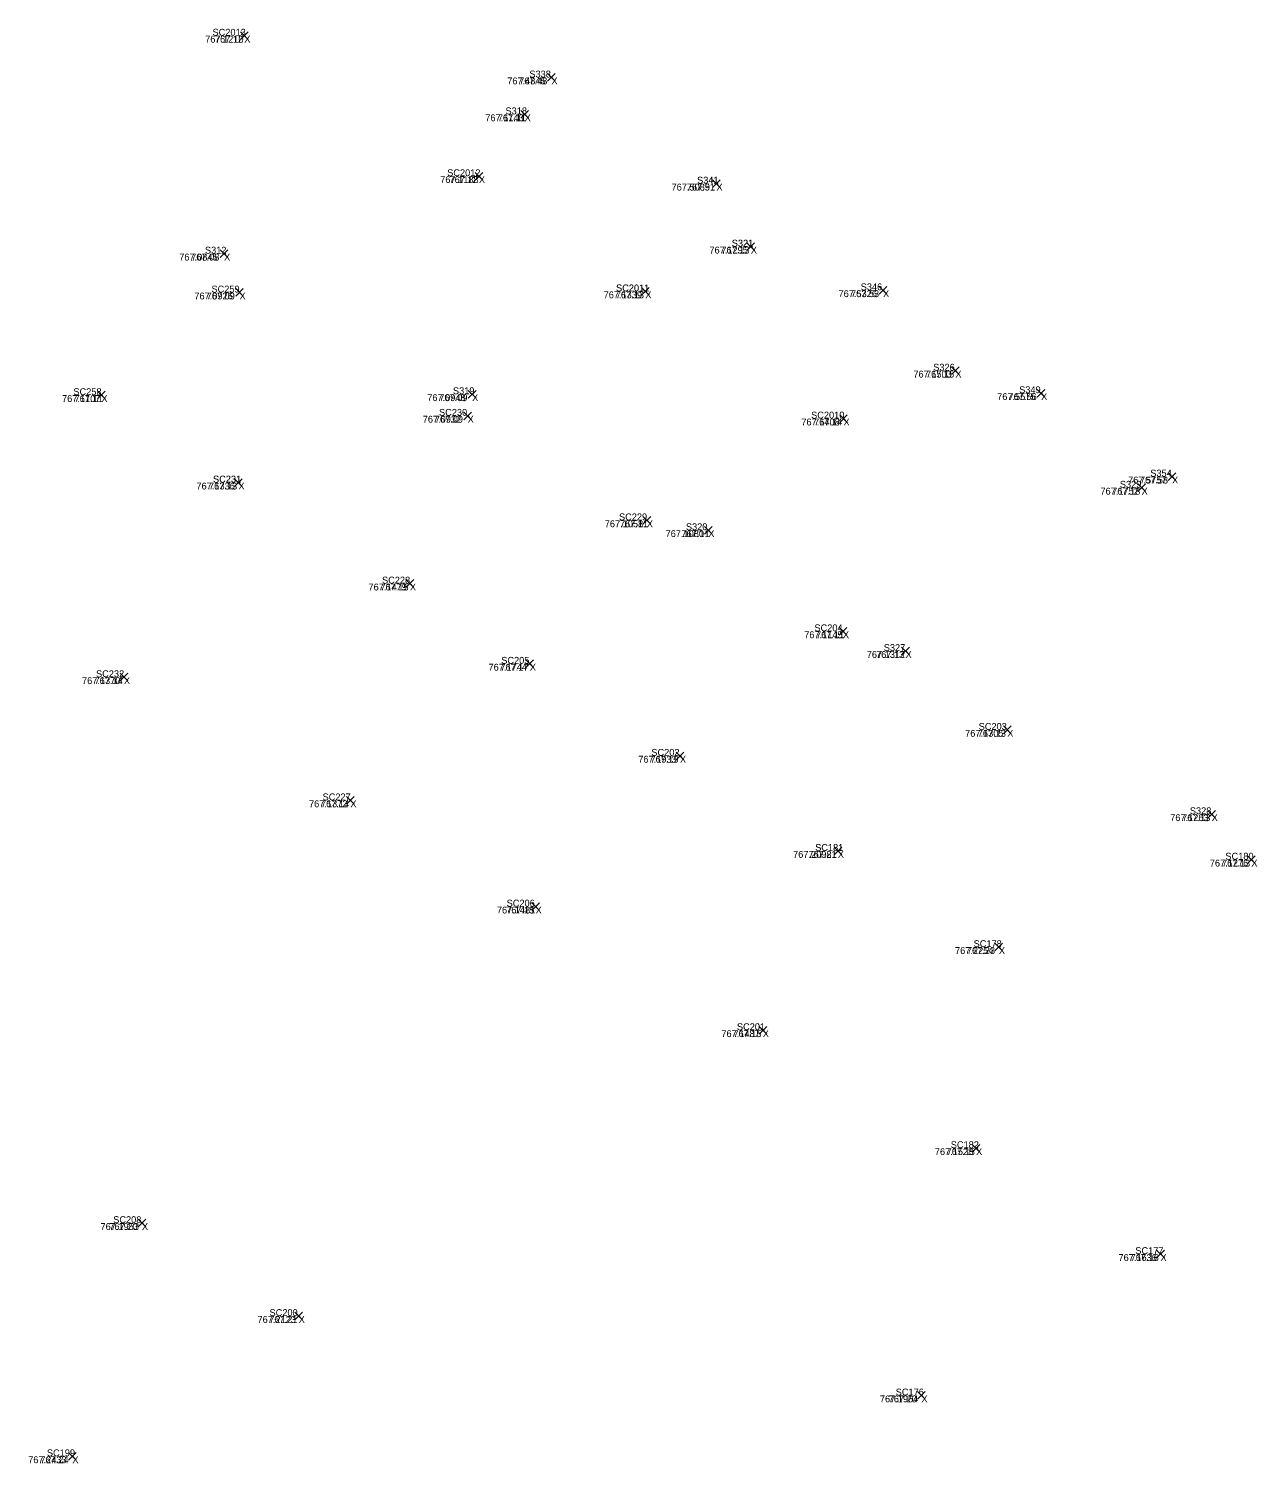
# Model space of a CAD drawing. Extents: x 1845019 to 1877956, y 680444 to 701081.
# Drawn here: x 1857674 to 1857684.7, y 694277.53 to 694290.04 of the extents above; entities that cross this region are included whole.
import ezdxf

# ---------------------------------------------------------------- set-up
doc = ezdxf.new("R2010")
doc.units = 0
for name, color, linetype in [('SV_X_Random_Point', 7, 'Continuous'), ('SV_X_Text_Comment', 7, 'Continuous'), ('SV_X_Text_Elevation', 7, 'Continuous'), ('SV_X_Text_Name', 7, 'Continuous')]:
    doc.layers.add(name, color=color, linetype=linetype)

msp = doc.modelspace()

# ---------------------------------------------------------------- linework, layer by layer
at = {"layer": 'SV_X_Random_Point'}
for p, q in [((1857675.845, 694289.941), (1857675.912, 694290.008)), ((1857675.845, 694290.008), (1857675.912, 694289.941)), ((1857675.845, 694289.941), (1857675.912, 694290.008)), ((1857675.845, 694290.008), (1857675.912, 694289.941)), ((1857678.521, 694289.577), (1857678.588, 694289.644)), ((1857678.521, 694289.644), (1857678.588, 694289.577)), ((1857678.521, 694289.577), (1857678.588, 694289.644)), ((1857678.521, 694289.644), (1857678.588, 694289.577)), ((1857678.287, 694289.255), (1857678.354, 694289.322)), ((1857678.287, 694289.322), (1857678.354, 694289.255)), ((1857678.287, 694289.255), (1857678.354, 694289.322)), ((1857678.287, 694289.322), (1857678.354, 694289.255)), ((1857677.889, 694288.716), (1857677.956, 694288.783)), ((1857677.889, 694288.783), (1857677.956, 694288.716)), ((1857677.889, 694288.716), (1857677.956, 694288.783)), ((1857677.889, 694288.783), (1857677.956, 694288.716)), ((1857679.958, 694288.651), (1857680.025, 694288.718)), ((1857679.958, 694288.718), (1857680.025, 694288.651)), ((1857679.958, 694288.651), (1857680.025, 694288.718)), ((1857679.958, 694288.718), (1857680.025, 694288.651)), ((1857680.258, 694288.103), (1857680.325, 694288.17)), ((1857680.258, 694288.17), (1857680.325, 694288.103)), ((1857680.258, 694288.103), (1857680.325, 694288.17)), ((1857680.258, 694288.17), (1857680.325, 694288.103)), ((1857675.668, 694288.042), (1857675.735, 694288.108)), ((1857675.668, 694288.108), (1857675.735, 694288.042)), ((1857675.668, 694288.042), (1857675.735, 694288.108)), ((1857675.668, 694288.108), (1857675.735, 694288.042)), ((1857675.803, 694287.703), (1857675.869, 694287.77)), ((1857675.803, 694287.77), (1857675.869, 694287.703)), ((1857675.803, 694287.703), (1857675.869, 694287.77)), ((1857675.803, 694287.77), (1857675.869, 694287.703)), ((1857679.339, 694287.712), (1857679.405, 694287.779)), ((1857679.339, 694287.779), (1857679.405, 694287.712)), ((1857679.339, 694287.712), (1857679.405, 694287.779)), ((1857679.339, 694287.779), (1857679.405, 694287.712)), ((1857681.411, 694287.723), (1857681.477, 694287.79)), ((1857681.411, 694287.79), (1857681.477, 694287.723)), ((1857681.411, 694287.723), (1857681.477, 694287.79)), ((1857681.411, 694287.79), (1857681.477, 694287.723)), ((1857682.041, 694287.021), (1857682.107, 694287.088)), ((1857682.041, 694287.088), (1857682.107, 694287.021)), ((1857682.041, 694287.021), (1857682.107, 694287.088)), ((1857682.041, 694287.088), (1857682.107, 694287.021)), ((1857674.599, 694286.809), (1857674.666, 694286.876)), ((1857674.599, 694286.876), (1857674.666, 694286.809)), ((1857674.599, 694286.809), (1857674.666, 694286.876)), ((1857674.599, 694286.876), (1857674.666, 694286.809)), ((1857677.83, 694286.816), (1857677.897, 694286.883)), ((1857677.83, 694286.883), (1857677.897, 694286.816)), ((1857677.83, 694286.816), (1857677.897, 694286.883)), ((1857677.83, 694286.883), (1857677.897, 694286.816)), ((1857682.788, 694286.825), (1857682.854, 694286.892)), ((1857682.788, 694286.892), (1857682.854, 694286.825)), ((1857682.788, 694286.825), (1857682.854, 694286.892)), ((1857682.788, 694286.892), (1857682.854, 694286.825)), ((1857677.791, 694286.628), (1857677.857, 694286.695)), ((1857677.791, 694286.695), (1857677.857, 694286.628)), ((1857677.791, 694286.628), (1857677.857, 694286.695)), ((1857677.791, 694286.695), (1857677.857, 694286.628)), ((1857681.066, 694286.604), (1857681.132, 694286.671)), ((1857681.066, 694286.671), (1857681.132, 694286.604)), ((1857681.066, 694286.604), (1857681.132, 694286.671)), ((1857681.066, 694286.671), (1857681.132, 694286.604)), ((1857683.929, 694286.099), (1857683.996, 694286.165)), ((1857683.929, 694286.165), (1857683.996, 694286.099)), ((1857683.929, 694286.099), (1857683.996, 694286.165)), ((1857683.929, 694286.165), (1857683.996, 694286.099)), ((1857675.794, 694286.047), (1857675.86, 694286.113)), ((1857675.794, 694286.113), (1857675.86, 694286.047)), ((1857675.794, 694286.047), (1857675.86, 694286.113)), ((1857675.794, 694286.113), (1857675.86, 694286.047)), ((1857683.664, 694286.001), (1857683.731, 694286.068)), ((1857683.664, 694286.068), (1857683.731, 694286.001)), ((1857683.664, 694286.001), (1857683.731, 694286.068)), ((1857683.664, 694286.068), (1857683.731, 694286.001)), ((1857679.352, 694285.718), (1857679.419, 694285.785)), ((1857679.352, 694285.785), (1857679.419, 694285.718)), ((1857679.352, 694285.718), (1857679.419, 694285.785)), ((1857679.352, 694285.785), (1857679.419, 694285.718)), ((1857679.887, 694285.631), (1857679.954, 694285.698)), ((1857679.887, 694285.698), (1857679.954, 694285.631)), ((1857679.887, 694285.631), (1857679.954, 694285.698)), ((1857679.887, 694285.698), (1857679.954, 694285.631)), ((1857677.287, 694285.167), (1857677.354, 694285.234)), ((1857677.287, 694285.234), (1857677.354, 694285.167)), ((1857677.287, 694285.167), (1857677.354, 694285.234)), ((1857677.287, 694285.234), (1857677.354, 694285.167)), ((1857681.061, 694284.751), (1857681.127, 694284.817)), ((1857681.061, 694284.817), (1857681.127, 694284.751)), ((1857681.061, 694284.751), (1857681.127, 694284.817)), ((1857681.061, 694284.817), (1857681.127, 694284.751)), ((1857681.606, 694284.579), (1857681.673, 694284.645)), ((1857681.606, 694284.645), (1857681.673, 694284.579)), ((1857681.606, 694284.579), (1857681.673, 694284.645)), ((1857681.606, 694284.645), (1857681.673, 694284.579)), ((1857678.332, 694284.468), (1857678.399, 694284.534)), ((1857678.332, 694284.534), (1857678.399, 694284.468)), ((1857678.332, 694284.468), (1857678.399, 694284.534)), ((1857678.332, 694284.534), (1857678.399, 694284.468)), ((1857674.796, 694284.351), (1857674.863, 694284.418)), ((1857674.796, 694284.418), (1857674.863, 694284.351)), ((1857674.796, 694284.351), (1857674.863, 694284.418)), ((1857674.796, 694284.418), (1857674.863, 694284.351)), ((1857682.492, 694283.892), (1857682.559, 694283.959)), ((1857682.492, 694283.959), (1857682.559, 694283.892)), ((1857682.492, 694283.892), (1857682.559, 694283.959)), ((1857682.492, 694283.959), (1857682.559, 694283.892)), ((1857679.64, 694283.665), (1857679.707, 694283.732)), ((1857679.64, 694283.732), (1857679.707, 694283.665)), ((1857679.64, 694283.665), (1857679.707, 694283.732)), ((1857679.64, 694283.732), (1857679.707, 694283.665)), ((1857676.769, 694283.278), (1857676.835, 694283.344)), ((1857676.769, 694283.344), (1857676.835, 694283.278)), ((1857676.769, 694283.278), (1857676.835, 694283.344)), ((1857676.769, 694283.344), (1857676.835, 694283.278)), ((1857684.273, 694283.157), (1857684.34, 694283.223)), ((1857684.273, 694283.223), (1857684.34, 694283.157)), ((1857684.273, 694283.157), (1857684.34, 694283.223)), ((1857684.273, 694283.223), (1857684.34, 694283.157)), ((1857681.017, 694282.837), (1857681.084, 694282.903)), ((1857681.017, 694282.903), (1857681.084, 694282.837)), ((1857681.017, 694282.837), (1857681.084, 694282.903)), ((1857681.017, 694282.903), (1857681.084, 694282.837)), ((1857684.62, 694282.76), (1857684.686, 694282.827)), ((1857684.62, 694282.827), (1857684.686, 694282.76)), ((1857684.62, 694282.76), (1857684.686, 694282.827)), ((1857684.62, 694282.827), (1857684.686, 694282.76)), ((1857678.383, 694282.352), (1857678.45, 694282.418)), ((1857678.383, 694282.418), (1857678.45, 694282.352)), ((1857678.383, 694282.352), (1857678.45, 694282.418)), ((1857678.383, 694282.418), (1857678.45, 694282.352)), ((1857682.419, 694281.999), (1857682.486, 694282.065)), ((1857682.419, 694282.065), (1857682.486, 694281.999)), ((1857682.419, 694281.999), (1857682.486, 694282.065)), ((1857682.419, 694282.065), (1857682.486, 694281.999)), ((1857680.363, 694281.274), (1857680.43, 694281.341)), ((1857680.363, 694281.341), (1857680.43, 694281.274)), ((1857680.363, 694281.274), (1857680.43, 694281.341)), ((1857680.363, 694281.341), (1857680.43, 694281.274)), ((1857682.221, 694280.246), (1857682.288, 694280.313)), ((1857682.221, 694280.313), (1857682.288, 694280.246)), ((1857682.221, 694280.246), (1857682.288, 694280.313)), ((1857682.221, 694280.313), (1857682.288, 694280.246)), ((1857674.953, 694279.594), (1857675.019, 694279.661)), ((1857674.953, 694279.661), (1857675.019, 694279.594)), ((1857674.953, 694279.594), (1857675.019, 694279.661)), ((1857674.953, 694279.661), (1857675.019, 694279.594)), ((1857683.828, 694279.323), (1857683.895, 694279.39)), ((1857683.828, 694279.39), (1857683.895, 694279.323)), ((1857683.828, 694279.323), (1857683.895, 694279.39)), ((1857683.828, 694279.39), (1857683.895, 694279.323)), ((1857676.319, 694278.783), (1857676.385, 694278.85)), ((1857676.319, 694278.85), (1857676.385, 694278.783)), ((1857676.319, 694278.783), (1857676.385, 694278.85)), ((1857676.319, 694278.85), (1857676.385, 694278.783)), ((1857681.744, 694278.092), (1857681.811, 694278.159)), ((1857681.744, 694278.159), (1857681.811, 694278.092)), ((1857681.744, 694278.092), (1857681.811, 694278.159)), ((1857681.744, 694278.159), (1857681.811, 694278.092)), ((1857674.346, 694277.561), (1857674.413, 694277.628)), ((1857674.346, 694277.628), (1857674.413, 694277.561)), ((1857674.346, 694277.561), (1857674.413, 694277.628)), ((1857674.346, 694277.628), (1857674.413, 694277.561))]:
    msp.add_line(p, q, dxfattribs=at)

# ---------------------------------------------------------------- texts
at = {"layer": 'SV_X_Text_Comment'}
for p in [(1857675.878, 694289.914), (1857678.554, 694289.55), (1857678.321, 694289.229), (1857677.922, 694288.69), (1857679.992, 694288.625), (1857680.292, 694288.076), (1857675.702, 694288.015), (1857681.444, 694287.696), (1857675.836, 694287.676), (1857679.372, 694287.686), (1857682.074, 694286.995), (1857674.633, 694286.782), (1857677.863, 694286.79), (1857682.821, 694286.799), (1857677.824, 694286.602), (1857681.099, 694286.578), (1857683.962, 694286.072), (1857675.827, 694286.02), (1857683.697, 694285.975), (1857679.385, 694285.691), (1857679.921, 694285.605), (1857677.321, 694285.14), (1857681.094, 694284.724), (1857678.366, 694284.441), (1857681.64, 694284.552), (1857674.829, 694284.324), (1857682.526, 694283.865), (1857679.674, 694283.639), (1857676.802, 694283.251), (1857684.307, 694283.13), (1857681.05, 694282.81), (1857684.653, 694282.734), (1857678.416, 694282.325), (1857682.453, 694281.972), (1857680.396, 694281.248), (1857682.255, 694280.22), (1857674.986, 694279.567), (1857683.861, 694279.297), (1857676.352, 694278.757), (1857681.778, 694278.065), (1857674.38, 694277.535)]:
    msp.add_text('X', height=0.06, dxfattribs=at).set_placement(p)
at = {"layer": 'SV_X_Text_Elevation'}
for s, p in [('767.1210', (1857675.537, 694289.914)), ('767.12', (1857675.622, 694289.914)), ('767.4845', (1857678.169, 694289.55)), ('767.48', (1857678.273, 694289.55)), ('767.1140', (1857677.978, 694289.229)), ('767.11', (1857678.087, 694289.229)), ('767.1188', (1857677.585, 694288.69)), ('767.12', (1857677.666, 694288.69)), ('767.5089', (1857679.601, 694288.625)), ('767.51', (1857679.734, 694288.625)), ('767.1295', (1857679.931, 694288.076)), ('767.13', (1857680.035, 694288.076)), ('767.0845', (1857675.311, 694288.015)), ('767.08', (1857675.415, 694288.015)), ('767.5326', (1857681.056, 694287.696)), ('767.53', (1857681.164, 694287.696)), ('767.0926', (1857675.443, 694287.676)), ('767.09', (1857675.55, 694287.676)), ('767.1339', (1857679.009, 694287.686)), ('767.13', (1857679.115, 694287.686)), ('767.1503', (1857681.708, 694286.995)), ('767.15', (1857681.818, 694286.995)), ('767.1107', (1857674.29, 694286.782)), ('767.11', (1857674.399, 694286.782)), ('767.0948', (1857677.472, 694286.79)), ('767.09', (1857677.577, 694286.79)), ('767.5575', (1857682.438, 694286.799)), ('767.56', (1857682.537, 694286.799)), ('767.0932', (1857677.433, 694286.602)), ('767.09', (1857677.538, 694286.602)), ('767.1408', (1857680.732, 694286.578)), ('767.14', (1857680.843, 694286.578)), ('767.5757', (1857683.579, 694286.072)), ('767.58', (1857683.682, 694286.072)), ('767.1336', (1857675.461, 694286.02)), ('767.13', (1857675.57, 694286.02)), ('767.1752', (1857683.338, 694285.975)), ('767.18', (1857683.44, 694285.975)), ('767.1058', (1857679.019, 694285.691)), ('767.11', (1857679.151, 694285.691)), ('767.1080', (1857679.549, 694285.605)), ('767.11', (1857679.687, 694285.605)), ('767.1479', (1857676.96, 694285.14)), ('767.15', (1857677.064, 694285.14)), ('767.1145', (1857680.757, 694284.724)), ('767.11', (1857680.86, 694284.724)), ('767.1744', (1857678.006, 694284.441)), ('767.17', (1857678.109, 694284.441)), ('767.1312', (1857681.302, 694284.552)), ('767.13', (1857681.383, 694284.552)), ('767.1370', (1857674.464, 694284.324)), ('767.14', (1857674.573, 694284.324)), ('767.1305', (1857682.159, 694283.865)), ('767.13', (1857682.269, 694283.865)), ('767.1933', (1857679.311, 694283.639)), ('767.19', (1857679.417, 694283.639)), ('767.1372', (1857676.442, 694283.251)), ('767.14', (1857676.546, 694283.251)), ('767.1263', (1857683.946, 694283.13)), ('767.13', (1857684.05, 694283.13)), ('767.2098', (1857680.66, 694282.81)), ('767.21', (1857680.794, 694282.81)), ('767.1276', (1857684.291, 694282.734)), ('767.13', (1857684.397, 694282.734)), ('767.1481', (1857678.079, 694282.325)), ('767.15', (1857678.16, 694282.325)), ('767.2254', (1857682.071, 694281.972)), ('767.23', (1857682.174, 694281.972)), ('767.1487', (1857680.035, 694281.248)), ('767.15', (1857680.14, 694281.248)), ('767.1528', (1857681.895, 694280.22)), ('767.15', (1857681.998, 694280.22)), ('767.1953', (1857674.625, 694279.567)), ('767.20', (1857674.702, 694279.567)), ('767.1636', (1857683.495, 694279.297)), ('767.16', (1857683.601, 694279.297)), ('767.2123', (1857675.993, 694278.757)), ('767.21', (1857676.095, 694278.757)), ('767.1964', (1857681.416, 694278.065)), ('767.20', (1857681.493, 694278.065)), ('767.2433', (1857673.995, 694277.535)), ('767.24', (1857674.101, 694277.535))]:
    msp.add_text(s, height=0.06, dxfattribs=at).set_placement(p)
at = {"layer": 'SV_X_Text_Name'}
for s, p in [('SC2013', (1857675.601, 694289.974)), ('SC2013', (1857675.601, 694289.974)), ('S338', (1857678.362, 694289.61)), ('S338', (1857678.362, 694289.61)), ('S318', (1857678.154, 694289.289)), ('S318', (1857678.154, 694289.289)), ('SC2012', (1857677.646, 694288.75)), ('SC2012', (1857677.646, 694288.75)), ('S341', (1857679.823, 694288.685)), ('S341', (1857679.824, 694288.685)), ('S312', (1857675.535, 694288.075)), ('S312', (1857675.535, 694288.075)), ('S321', (1857680.125, 694288.136)), ('S321', (1857680.126, 694288.136)), ('SC259', (1857675.592, 694287.736)), ('SC259', (1857675.592, 694287.736)), ('SC2011', (1857679.117, 694287.746)), ('SC2011', (1857679.118, 694287.746)), ('S346', (1857681.249, 694287.756)), ('S346', (1857681.249, 694287.756)), ('S326', (1857681.881, 694287.055)), ('S326', (1857681.881, 694287.055)), ('SC258', (1857674.389, 694286.842)), ('SC258', (1857674.389, 694286.842)), ('S319', (1857677.696, 694286.85)), ('S319', (1857677.696, 694286.85)), ('S349', (1857682.63, 694286.859)), ('S349', (1857682.63, 694286.859)), ('SC230', (1857677.575, 694286.662)), ('SC230', (1857677.575, 694286.662)), ('SC2010', (1857680.817, 694286.638)), ('SC2010', (1857680.817, 694286.638)), ('SC231', (1857675.605, 694286.08)), ('SC231', (1857675.606, 694286.08)), ('S354', (1857683.772, 694286.132)), ('S354', (1857683.772, 694286.132)), ('S329', (1857683.507, 694286.035)), ('S329', (1857683.507, 694286.035)), ('SC229', (1857679.143, 694285.751)), ('SC229', (1857679.143, 694285.751)), ('S320', (1857679.726, 694285.665)), ('S320', (1857679.726, 694285.665)), ('SC228', (1857677.078, 694285.2)), ('SC228', (1857677.078, 694285.2)), ('SC204', (1857680.846, 694284.784)), ('SC204', (1857680.846, 694284.784)), ('S327', (1857681.45, 694284.612)), ('S327', (1857681.45, 694284.612)), ('SC205', (1857678.117, 694284.501)), ('SC205', (1857678.117, 694284.501)), ('SC232', (1857674.586, 694284.384)), ('SC232', (1857674.586, 694284.384)), ('SC203', (1857682.277, 694283.925)), ('SC203', (1857682.277, 694283.925)), ('SC202', (1857679.425, 694283.699)), ('SC202', (1857679.425, 694283.699)), ('SC227', (1857676.56, 694283.311)), ('SC227', (1857676.56, 694283.311)), ('S328', (1857684.117, 694283.19)), ('S328', (1857684.117, 694283.19)), ('SC181', (1857680.852, 694282.87)), ('SC181', (1857680.853, 694282.87)), ('SC180', (1857684.427, 694282.794)), ('SC180', (1857684.427, 694282.794)), ('SC206', (1857678.164, 694282.385)), ('SC206', (1857678.164, 694282.385)), ('SC178', (1857682.233, 694282.032)), ('SC178', (1857682.233, 694282.032)), ('SC201', (1857680.17, 694281.308)), ('SC201', (1857680.171, 694281.308)), ('SC182', (1857682.034, 694280.28)), ('SC182', (1857682.034, 694280.28)), ('SC208', (1857674.736, 694279.627)), ('SC208', (1857674.736, 694279.627)), ('SC177', (1857683.642, 694279.357)), ('SC177', (1857683.642, 694279.357)), ('SC200', (1857676.098, 694278.817)), ('SC200', (1857676.098, 694278.817)), ('SC176', (1857681.554, 694278.125)), ('SC176', (1857681.554, 694278.125)), ('SC199', (1857674.158, 694277.595)), ('SC199', (1857674.158, 694277.595))]:
    msp.add_text(s, height=0.06, dxfattribs=at).set_placement(p)

doc.saveas('drawing.dxf')
